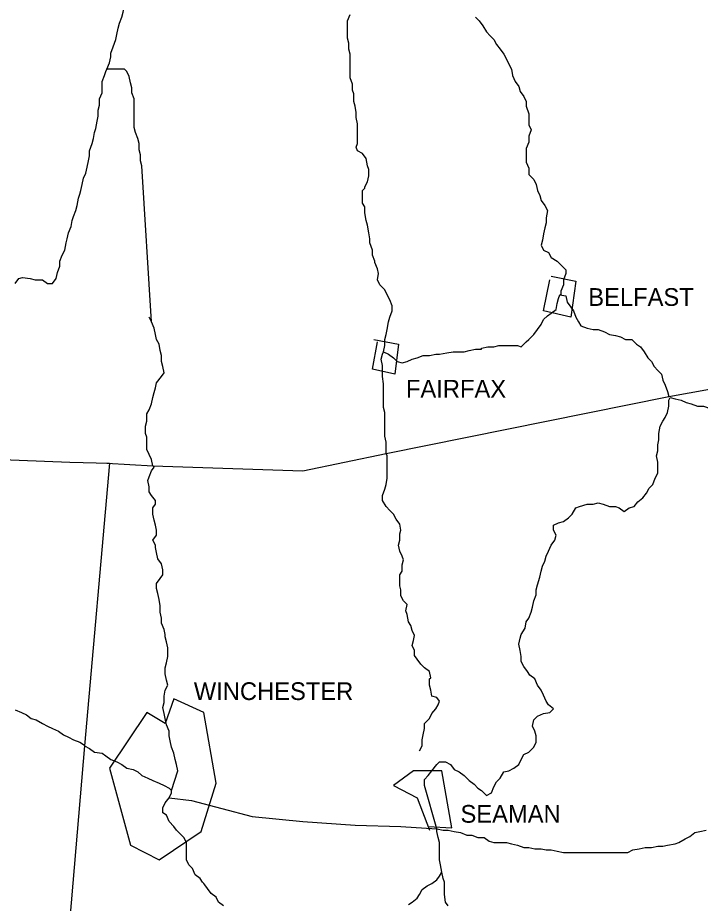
# Model space of a CAD drawing. Extents: x 0 to 40.2, y 0 to 22.
# Drawn here: x 3.548 to 4.298, y 17.238 to 18.212 of the extents above; entities that cross this region are included whole.
import ezdxf

# ---------------------------------------------------------------- set-up
doc = ezdxf.new("R2010")
doc.units = 0
doc.layers.add('Default', color=7, linetype='Continuous')

msp = doc.modelspace()

# ---------------------------------------------------------------- linework, layer by layer
at = {"layer": 'Default'}
for points in [[(2.98345, 18.75772), (2.963, 18.06237), (2.94527, 17.73515), (3.29158, 17.72561), (3.49337, 17.72697), (3.60517, 17.72288), (3.6488, 17.72152)], [(3.64607, 18.15508), (3.6488, 18.1619), (3.65016, 18.16872), (3.65016, 18.17281), (3.65289, 18.17963), (3.65562, 18.18781), (3.65698, 18.19326), (3.65834, 18.20008), (3.65971, 18.20553), (3.66243, 18.21235), (3.6638, 18.2178), (3.66516, 18.22462), (3.66516, 18.23007)], [(3.92148, 18.08828), (3.92148, 18.09509), (3.92012, 18.10191), (3.92012, 18.10736), (3.91876, 18.11418), (3.91739, 18.11963), (3.91739, 18.12782), (3.91603, 18.13191), (3.91603, 18.13872), (3.9133, 18.14554), (3.9133, 18.15236), (3.9133, 18.15781), (3.9133, 18.16326), (3.9133, 18.17144), (3.91194, 18.1769), (3.91194, 18.18372), (3.91058, 18.18917), (3.91058, 18.19599), (3.91058, 18.2028), (3.91058, 18.20826), (3.9133, 18.21507)], [(4.05101, 18.21235), (4.0551, 18.20826), (4.05919, 18.2028), (4.06328, 18.19599), (4.06737, 18.1919), (4.07146, 18.18781), (4.07419, 18.18235), (4.07828, 18.1769), (4.08237, 18.17144), (4.08509, 18.16599), (4.08782, 18.16054), (4.09055, 18.15508), (4.09191, 18.14827), (4.09464, 18.14145), (4.09873, 18.136), (4.10009, 18.13054), (4.10418, 18.12509), (4.10691, 18.11963), (4.10691, 18.11418), (4.10964, 18.106), (4.10964, 18.09918), (4.10964, 18.09373), (4.11236, 18.08828), (4.10964, 18.08146), (4.10964, 18.07464), (4.10691, 18.06782), (4.10691, 18.0651), (4.10691, 18.06373)], [(3.61744, 18.02147), (3.6188, 18.02829), (3.62017, 18.0351), (3.62289, 18.04056), (3.62426, 18.04737), (3.62562, 18.05419), (3.62699, 18.05964), (3.62699, 18.0651), (3.62971, 18.07328), (3.63108, 18.07873), (3.63244, 18.08555), (3.6338, 18.08964), (3.63517, 18.09782), (3.63653, 18.10327), (3.63653, 18.11009), (3.63789, 18.11554), (3.63789, 18.12236), (3.64062, 18.12918), (3.64062, 18.136), (3.64062, 18.14145), (3.64335, 18.14827), (3.64471, 18.15236), (3.64607, 18.15508)], [(3.68425, 18.04874), (3.68289, 18.05419), (3.68289, 18.06101), (3.68152, 18.06646), (3.68152, 18.07328), (3.68016, 18.07873), (3.67743, 18.08555), (3.67607, 18.091), (3.67607, 18.09782), (3.67607, 18.10327), (3.67607, 18.11009), (3.67607, 18.11691), (3.67607, 18.12236), (3.67334, 18.12918), (3.67334, 18.13463), (3.67198, 18.14009), (3.67061, 18.1469), (3.66789, 18.15236), (3.66516, 18.15508), (3.65834, 18.15508), (3.65153, 18.15508), (3.64607, 18.15508)], [(3.92966, 18.02556), (3.93239, 18.03101), (3.93375, 18.03783), (3.93375, 18.04465), (3.93239, 18.04874), (3.93103, 18.05692), (3.92694, 18.06237), (3.92148, 18.0651), (3.92012, 18.06919), (3.92148, 18.07328), (3.92148, 18.0801), (3.92148, 18.08691), (3.92148, 18.08691), (3.92148, 18.08828)], [(4.10691, 18.06373), (4.10691, 18.05692), (4.10691, 18.05283), (4.10964, 18.04601), (4.10964, 18.03919), (4.11509, 18.03374), (4.11782, 18.02829), (4.11918, 18.02147), (4.12191, 18.01601), (4.12327, 18.01056), (4.12736, 18.00511), (4.13009, 17.99965), (4.12872, 17.99147), (4.12872, 17.98602), (4.12736, 17.98057), (4.126, 17.97375), (4.12463, 17.96693), (4.12327, 17.96148), (4.126, 17.95602), (4.13145, 17.9533), (4.13418, 17.94784), (4.14099, 17.94375), (4.14509, 17.93966), (4.15054, 17.93421), (4.15054, 17.93012), (4.14781, 17.9233), (4.14781, 17.91785), (4.14509, 17.91103), (4.14509, 17.90694), (4.14372, 17.90694)], [(3.69516, 17.87695), (3.68425, 18.04874)], [(3.94057, 17.94375), (3.93785, 17.95057), (3.93785, 17.95602), (3.93512, 17.9642), (3.93512, 17.9683), (3.93375, 17.97511), (3.93239, 17.98329), (3.93103, 17.98875), (3.92966, 17.99693), (3.92966, 18.00374), (3.92694, 18.00783), (3.92694, 18.01601), (3.92694, 18.02147), (3.92966, 18.0242), (3.92966, 18.02556)], [(3.54518, 17.91921), (3.54927, 17.92467), (3.55336, 17.92603), (3.56154, 17.92467), (3.56699, 17.9233), (3.57518, 17.9233), (3.58063, 17.91921), (3.58608, 17.91921), (3.59017, 17.92467), (3.59154, 17.93148), (3.59426, 17.9383), (3.59426, 17.94375), (3.59699, 17.95057), (3.59972, 17.95602), (3.60108, 17.9642), (3.60244, 17.9683), (3.60381, 17.97511), (3.60653, 17.98193), (3.6079, 17.98875), (3.60926, 17.99284), (3.61199, 17.99965), (3.61335, 18.00511), (3.61471, 18.01329), (3.61608, 18.01738), (3.61744, 18.02147), (3.61744, 18.02147)], [(3.95012, 17.84422), (3.95148, 17.85104), (3.95148, 17.85786), (3.95284, 17.86331), (3.95421, 17.86877), (3.95557, 17.87695), (3.95693, 17.8824), (3.95966, 17.88922), (3.95966, 17.89467), (3.95693, 17.90149), (3.95421, 17.90694), (3.95148, 17.91239), (3.94603, 17.91785), (3.9433, 17.9233), (3.94466, 17.93012), (3.9433, 17.93557), (3.94057, 17.94239), (3.94057, 17.94375), (3.94057, 17.94375)], [(4.13418, 17.92739), (4.16145, 17.92194), (4.15599, 17.8824), (4.126, 17.88922), (4.13281, 17.9233)], [(4.05783, 17.84831), (4.06464, 17.84968), (4.07146, 17.84968), (4.07691, 17.85104), (4.08237, 17.85104), (4.09055, 17.85104), (4.09737, 17.85104), (4.10146, 17.84968), (4.10691, 17.85513), (4.10964, 17.85786), (4.11509, 17.86331), (4.11918, 17.86877), (4.12327, 17.87422), (4.126, 17.87967), (4.13009, 17.88376), (4.13418, 17.88649), (4.13963, 17.89058), (4.14099, 17.8974), (4.14236, 17.90285), (4.14372, 17.90694)], [(4.14372, 17.90694), (4.15054, 17.90558), (4.1519, 17.89876), (4.15599, 17.89331), (4.15872, 17.88922), (4.16145, 17.8824), (4.16417, 17.87695), (4.1669, 17.87286), (4.17372, 17.87013), (4.18053, 17.86877), (4.18599, 17.86877), (4.1928, 17.86604), (4.19826, 17.86331), (4.20508, 17.86195), (4.21053, 17.86058), (4.21598, 17.85786), (4.2228, 17.85786), (4.22825, 17.8524), (4.23234, 17.84968), (4.23643, 17.84422), (4.24052, 17.83741), (4.24461, 17.83332), (4.24734, 17.82786), (4.25143, 17.82377), (4.25552, 17.81968), (4.25689, 17.81287), (4.25961, 17.80741), (4.26234, 17.80059), (4.2637, 17.79514)], [(3.69652, 17.71879), (3.69516, 17.72561), (3.69243, 17.73106), (3.6897, 17.73651), (3.6897, 17.74333), (3.6897, 17.75015), (3.68834, 17.75424), (3.68834, 17.76242), (3.6897, 17.76787), (3.6897, 17.77605), (3.69243, 17.78014), (3.69516, 17.78696), (3.69652, 17.79378), (3.69788, 17.79923), (3.69925, 17.80468), (3.70061, 17.81014), (3.70606, 17.81696), (3.70879, 17.82105), (3.70743, 17.82786), (3.70606, 17.83332), (3.70606, 17.84013), (3.7047, 17.84559), (3.70334, 17.8524), (3.70061, 17.85786), (3.69925, 17.86331), (3.69788, 17.87013), (3.69516, 17.87695), (3.69243, 17.8824), (3.69243, 17.8824)], [(3.64607, 17.72152), (3.69652, 17.71879), (3.86149, 17.71334), (3.95284, 17.73242), (4.2637, 17.79514), (4.64137, 17.86331), (4.66182, 17.86877)], [(3.93921, 17.85786), (3.96648, 17.8524), (3.96239, 17.81968), (3.93785, 17.82514), (3.9433, 17.85513)], [(3.95012, 17.84422), (3.95557, 17.8415), (3.96102, 17.83741), (3.96511, 17.83332), (3.97057, 17.83195), (3.97602, 17.83332), (3.98147, 17.83604), (3.98693, 17.83741), (3.99375, 17.84013), (4.00056, 17.84013), (4.00738, 17.8415), (4.01147, 17.8415), (4.01965, 17.84286), (4.02647, 17.84422), (4.03192, 17.84422), (4.03874, 17.84422), (4.04419, 17.84559), (4.05101, 17.84695), (4.05783, 17.84695), (4.05783, 17.84831)], [(3.95284, 17.73242), (3.95284, 17.73924), (3.95284, 17.74469), (3.95148, 17.75151), (3.95148, 17.75833), (3.95148, 17.76378), (3.95148, 17.7706), (3.95148, 17.77742), (3.95012, 17.78287), (3.95012, 17.78969), (3.95012, 17.7965), (3.95012, 17.80332), (3.95012, 17.80877), (3.94875, 17.81696), (3.94875, 17.82241), (3.94875, 17.82923), (3.94739, 17.83604), (3.94875, 17.8415), (3.95012, 17.84422)], [(4.1369, 17.45156), (4.13145, 17.45565), (4.12872, 17.45974), (4.126, 17.46656), (4.12327, 17.47201), (4.11918, 17.47746), (4.11645, 17.48428), (4.111, 17.48837), (4.10827, 17.49246), (4.10418, 17.49791), (4.10146, 17.50337), (4.10146, 17.50882), (4.10009, 17.51564), (4.09873, 17.52246), (4.10009, 17.52927), (4.10146, 17.53336), (4.10555, 17.54018), (4.10691, 17.547), (4.10964, 17.55109), (4.11236, 17.55791), (4.11373, 17.56336), (4.11509, 17.57018), (4.11782, 17.57699), (4.11782, 17.58245), (4.11918, 17.5879), (4.12191, 17.59608), (4.12327, 17.6029), (4.12463, 17.60835), (4.12736, 17.61381), (4.12872, 17.61926), (4.13145, 17.62471), (4.13418, 17.63153), (4.13827, 17.63698), (4.13963, 17.64244), (4.1369, 17.64789), (4.1369, 17.65334), (4.14236, 17.65607), (4.14781, 17.65744), (4.15327, 17.66153), (4.15736, 17.66562), (4.16145, 17.67243), (4.16554, 17.6738), (4.17372, 17.67652), (4.18053, 17.67652), (4.18599, 17.67789), (4.19144, 17.67652), (4.19826, 17.6738), (4.20508, 17.6738), (4.20917, 17.67243), (4.21462, 17.66834), (4.22007, 17.67243), (4.22553, 17.6738), (4.22962, 17.67925), (4.23507, 17.68334), (4.23916, 17.68879), (4.24189, 17.69425), (4.24598, 17.69834), (4.24871, 17.70515), (4.25143, 17.71061), (4.25143, 17.71743), (4.25143, 17.72288), (4.25007, 17.7297), (4.25143, 17.73515), (4.25143, 17.74197), (4.2528, 17.74742), (4.2528, 17.75424), (4.25416, 17.76242), (4.25689, 17.76787), (4.25961, 17.77196), (4.26234, 17.77742), (4.2637, 17.78423), (4.2637, 17.79105), (4.26507, 17.79378)], [(4.26507, 17.79378), (4.27052, 17.79241), (4.27734, 17.79105), (4.28279, 17.78832), (4.28824, 17.78696), (4.29506, 17.78423), (4.30188, 17.78423), (4.30597, 17.78287), (4.31142, 17.77742), (4.31415, 17.77196), (4.3196, 17.76924), (4.32506, 17.76515), (4.33051, 17.76242), (4.3346, 17.75833), (4.33733, 17.75833)], [(3.9692, 17.64789), (3.96784, 17.65471), (3.96375, 17.66016), (3.96102, 17.66562), (3.95693, 17.66971), (3.95284, 17.6738), (3.94875, 17.68061), (3.94875, 17.68607), (3.95148, 17.69288), (3.95284, 17.69834), (3.95421, 17.70515), (3.95421, 17.71061), (3.95421, 17.71743), (3.95421, 17.72288), (3.95421, 17.7297), (3.95284, 17.73242)], [(3.6488, 17.72152), (3.62153, 17.41066), (3.56836, 16.78485), (3.52064, 16.19721), (3.51109, 16.02406), (3.50973, 16.00088)], [(3.69925, 17.63153), (3.69652, 17.63698), (3.70061, 17.64244), (3.70061, 17.64789), (3.69925, 17.65334), (3.69788, 17.6588), (3.69652, 17.66562), (3.69652, 17.67243), (3.69925, 17.67652), (3.69925, 17.68061), (3.69516, 17.68607), (3.69243, 17.69016), (3.69243, 17.69561), (3.69107, 17.70243), (3.69243, 17.70652), (3.69516, 17.71334), (3.69788, 17.71743), (3.69652, 17.71879), (3.69652, 17.71879)], [(4.00193, 17.48564), (4.00056, 17.49246), (3.99511, 17.49655), (3.99102, 17.50064), (3.98693, 17.5061), (3.9842, 17.51019), (3.9842, 17.51564), (3.98147, 17.52109), (3.98284, 17.52655), (3.9842, 17.532), (3.98147, 17.53745), (3.98011, 17.54291), (3.97738, 17.547), (3.97602, 17.55518), (3.97466, 17.55927), (3.97602, 17.56609), (3.97193, 17.57018), (3.9692, 17.57563), (3.9692, 17.58245), (3.96784, 17.58654), (3.96784, 17.59199), (3.96784, 17.59881), (3.97057, 17.6029), (3.97057, 17.60972), (3.97193, 17.61517), (3.97057, 17.61926), (3.96784, 17.62471), (3.96648, 17.63153), (3.96784, 17.63698), (3.96784, 17.6438), (3.9692, 17.64789), (3.9692, 17.64789), (3.9692, 17.64789)], [(3.71015, 17.53336), (3.70879, 17.53882), (3.70606, 17.54563), (3.70606, 17.55109), (3.7047, 17.55791), (3.7047, 17.56472), (3.70334, 17.57154), (3.70197, 17.57836), (3.70061, 17.58381), (3.70061, 17.58926), (3.7047, 17.59472), (3.70743, 17.59881), (3.70743, 17.60426), (3.70606, 17.61108), (3.70197, 17.61653), (3.70061, 17.62335), (3.69925, 17.6288), (3.69925, 17.63153), (3.69925, 17.63153)], [(3.71697, 17.36157), (3.72379, 17.38339), (3.72242, 17.3902), (3.72106, 17.39566), (3.7197, 17.40248), (3.71697, 17.40929), (3.71561, 17.41611), (3.71424, 17.42156), (3.71424, 17.42702), (3.71152, 17.43383), (3.71015, 17.44065), (3.70879, 17.4461), (3.70743, 17.45292), (3.70879, 17.45838), (3.70879, 17.46519), (3.71015, 17.47201), (3.71288, 17.47746), (3.71152, 17.48292), (3.71015, 17.48973), (3.71015, 17.49655), (3.71152, 17.50201), (3.71288, 17.50882), (3.71288, 17.51155), (3.71288, 17.51837), (3.71152, 17.52518), (3.71015, 17.53064), (3.71015, 17.53336)], [(3.98966, 17.4052), (3.99238, 17.41066), (3.99238, 17.41747), (3.99375, 17.42293), (3.99511, 17.42974), (3.99511, 17.4352), (4.00056, 17.44065), (4.00329, 17.4461), (4.00738, 17.45156), (4.01011, 17.45565), (4.01147, 17.45974), (4.00874, 17.46383), (4.00329, 17.46519), (4.00193, 17.47201), (4.00056, 17.47746), (4.00056, 17.48428), (4.00193, 17.48564)], [(3.67198, 17.30158), (3.70334, 17.28522), (3.74969, 17.31658), (3.76605, 17.36975), (3.75242, 17.44747), (3.7197, 17.46247), (3.71015, 17.4352), (3.6897, 17.44747), (3.6488, 17.38611), (3.67198, 17.30158)], [(3.54518, 17.4502), (3.552, 17.44747), (3.55745, 17.44474), (3.5629, 17.44065), (3.56836, 17.43929), (3.57518, 17.4352), (3.58063, 17.43247), (3.58608, 17.42974), (3.5929, 17.42702), (3.59835, 17.42293), (3.60381, 17.4202), (3.60926, 17.41747), (3.61608, 17.41475), (3.62017, 17.41202), (3.62153, 17.41066)], [(3.99511, 17.37384), (3.9992, 17.37793), (4.00329, 17.38339), (4.00874, 17.3902), (4.01147, 17.39293), (4.01829, 17.39293), (4.02374, 17.3902), (4.02783, 17.38475), (4.03328, 17.38202), (4.03874, 17.37793), (4.04419, 17.37248), (4.04965, 17.36839), (4.05374, 17.3643), (4.05783, 17.36157), (4.06328, 17.35612), (4.06873, 17.35885), (4.07146, 17.36566), (4.07419, 17.37112), (4.07828, 17.37521), (4.08237, 17.38202), (4.08782, 17.38339), (4.09328, 17.38611), (4.09873, 17.3902), (4.10146, 17.39566), (4.10418, 17.40111), (4.10964, 17.40384), (4.11509, 17.40929), (4.11782, 17.41475), (4.11782, 17.42156), (4.11645, 17.42702), (4.11373, 17.43247), (4.11509, 17.43929), (4.11918, 17.44338), (4.126, 17.4461), (4.13281, 17.44747), (4.1369, 17.45156), (4.1369, 17.45156)], [(3.62153, 17.41066), (3.62699, 17.40793), (3.63244, 17.40384), (3.64062, 17.40248), (3.64471, 17.39975), (3.65016, 17.39566), (3.65698, 17.39293), (3.66243, 17.3902), (3.66789, 17.38611), (3.6747, 17.38475), (3.68016, 17.38202), (3.68425, 17.37793), (3.69107, 17.37521), (3.69652, 17.37248), (3.70334, 17.36975), (3.70879, 17.36703), (3.71424, 17.3643), (3.71697, 17.36157), (3.71697, 17.36157)], [(3.9992, 17.32203), (4.0251, 17.32067), (4.0142, 17.38339), (3.98284, 17.38339), (3.96102, 17.36703), (3.98693, 17.35339), (4.00056, 17.31794)], [(4.00874, 17.31931), (3.99511, 17.36703), (3.99511, 17.37384)], [(3.7197, 17.32203), (3.71424, 17.32749), (3.71152, 17.3343), (3.70743, 17.33703), (3.70743, 17.34249), (3.71015, 17.34794), (3.71424, 17.35339), (3.71697, 17.35885), (3.71697, 17.36157)], [(3.71424, 17.35339), (3.73879, 17.35067), (3.80559, 17.33294), (3.86149, 17.32749), (3.91876, 17.3234), (3.9692, 17.32203), (4.00874, 17.31931)], [(3.75106, 17.26068), (3.74833, 17.26477), (3.74288, 17.26886), (3.74015, 17.27568), (3.73606, 17.27977), (3.73333, 17.28522), (3.73333, 17.2934), (3.73333, 17.29886), (3.73333, 17.30431), (3.73061, 17.30976), (3.72788, 17.31249), (3.72242, 17.31794), (3.7197, 17.32203), (3.7197, 17.32203)], [(4.00874, 17.31931), (4.01556, 17.31794), (4.02101, 17.31794), (4.02783, 17.31658), (4.03465, 17.31522), (4.04147, 17.31249), (4.04692, 17.31249), (4.05374, 17.30976), (4.06055, 17.30976), (4.06601, 17.30567), (4.07146, 17.30431), (4.07691, 17.30431), (4.08509, 17.30431), (4.09055, 17.30295), (4.09737, 17.30158), (4.10418, 17.29886), (4.10964, 17.29886), (4.11645, 17.29749), (4.12327, 17.29749), (4.12872, 17.29613), (4.13418, 17.29613), (4.14099, 17.29477), (4.14781, 17.2934), (4.15599, 17.2934), (4.16145, 17.2934), (4.1669, 17.2934), (4.17372, 17.2934), (4.18053, 17.2934), (4.18735, 17.2934), (4.1928, 17.2934), (4.19826, 17.2934), (4.20508, 17.2934), (4.21189, 17.2934), (4.21871, 17.2934), (4.22416, 17.29613), (4.23098, 17.29749), (4.2378, 17.29886), (4.24461, 17.29886), (4.25143, 17.30022), (4.25689, 17.30022), (4.26234, 17.30158), (4.27052, 17.30295), (4.27461, 17.30431), (4.28143, 17.3084), (4.28688, 17.31113), (4.29233, 17.31522), (4.29779, 17.31658), (4.30461, 17.31794)], [(4.0142, 17.27159), (4.01283, 17.27977), (4.01147, 17.28522), (4.01147, 17.29204), (4.01147, 17.29886), (4.01147, 17.30431), (4.01011, 17.30976), (4.00874, 17.31658), (4.00874, 17.31931)], [(3.97738, 17.23614), (3.98147, 17.23887), (3.98693, 17.24296), (3.98966, 17.24705), (3.99238, 17.2525), (3.99784, 17.25659), (4.00329, 17.25932), (4.00874, 17.26341), (4.01147, 17.2675), (4.0142, 17.27159), (4.0142, 17.27159), (4.0142, 17.27159)], [(4.02101, 17.23477), (4.01829, 17.23887), (4.01692, 17.24705), (4.01692, 17.2525), (4.01692, 17.26068), (4.01556, 17.26477), (4.0142, 17.27159), (4.0142, 17.27159)], [(3.77423, 17.23477), (3.76878, 17.23887), (3.76605, 17.24432), (3.7606, 17.24841), (3.75651, 17.25386), (3.75378, 17.25795), (3.75242, 17.25932), (3.75106, 17.26068)]]:
    msp.add_lwpolyline(points, dxfattribs=at)

# ---------------------------------------------------------------- texts
for s, p in [('BELFAST', (4.17508, 17.89467)), ('FAIRFAX', (3.97466, 17.79378)), ('WINCHESTER', (3.74151, 17.4611)), ('SEAMAN', (4.03465, 17.32612))]:
    msp.add_text(s, height=0.019502, dxfattribs=at).set_placement(p)

doc.saveas('drawing.dxf')
